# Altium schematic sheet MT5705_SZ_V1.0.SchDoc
size A4; PageSetup: Record=PageOptions¦CenterHorizontal=True¦CenterVertical=True¦PrintScale=1.00¦XCorrection=1.00¦YCorrection=1.00¦PrintKind=0¦BorderSize=5000000¦LeftOffset=0¦BottomOffset=0¦Orientation=2¦PaperLength=1000¦PaperWidth=1000¦Scale=100¦PaperSource=7¦PrintQuality=-4¦MediaType=1¦DitherType=10¦PrintScaleMode=1¦PaperKind=A4¦PaperIndex=9
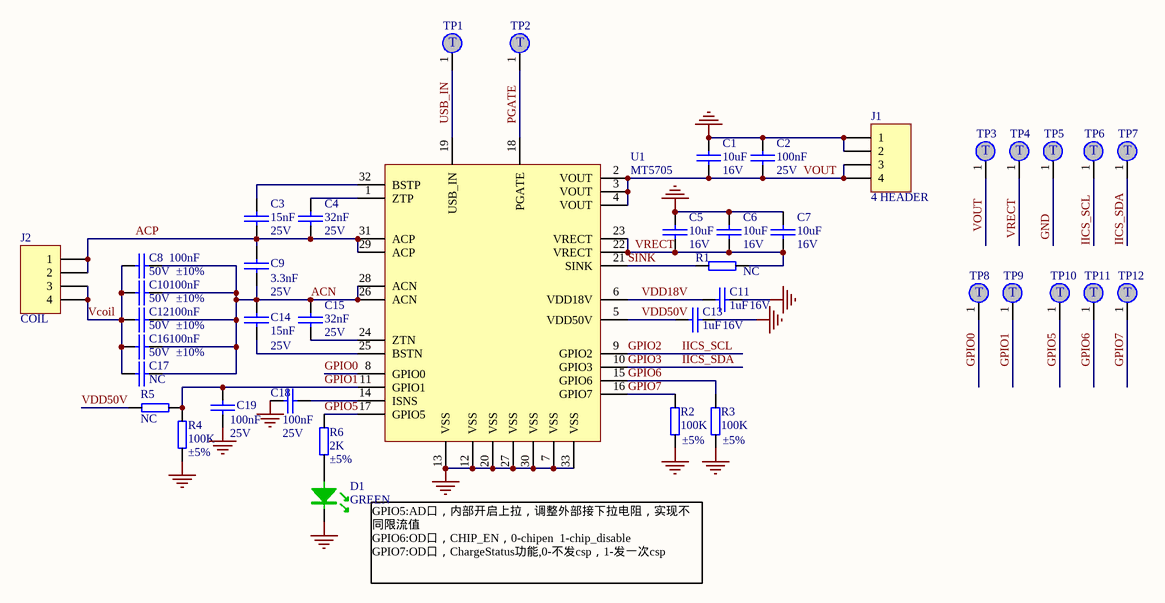
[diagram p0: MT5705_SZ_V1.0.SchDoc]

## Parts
C1  10uF  耐压: 16V  [0603C]
C2  100nF  耐压: 25V  [0402C]
C3  15nF  耐压: 25V  [0402C]
C4  32nF  耐压: 25V  [0402C]
C5  10uF  耐压: 16V  [0603C]
C6  10uF  耐压: 16V  [0603C]
C7  10uF  耐压: 16V  [0603C]
C8  100nF  耐压: 50V  精度: ±10%  [0402C]
C9  3.3nF  耐压: 25V  [0402C]
C10  100nF  耐压: 50V  精度: ±10%  [0402C]
C11  1uF  耐压: 16V  [0402C]
C12  100nF  耐压: 50V  精度: ±10%  [0402C]
C13  1uF  耐压: 16V  [0402C]
C14  15nF  耐压: 25V  [0402C]
C15  32nF  耐压: 25V  [0402C]
C16  100nF  耐压: 50V  精度: ±10%  [0402C]
C17  NC  [0402C]
C18  100nF  耐压: 25V  [0402C]
C19  100nF  耐压: 25V  [0402C]
D1  GREEN  [D0603]
J1  4 HEADER  [SIP4-2.00mm]
J2  COIL  [SIP4-2.00mm]
R1  NC  [0603R]
R2  100K  精度: ±5%  [0402R]
R3  100K  精度: ±5%  [0402R]
R4  100K  精度: ±5%  [0402R]
R5  NC  [0402R]
R6  2K  精度: ±5%  [0402R]
TP1  (no value)  [TEST-PAD-S]
TP2  (no value)  [TEST-PAD-S]
TP3  (no value)  [TEST-PAD-S]
TP4  (no value)  [TEST-PAD-S]
TP5  (no value)  [TEST-PAD-S]
TP6  (no value)  [TEST-PAD-S]
TP7  (no value)  [TEST-PAD-S]
TP8  (no value)  [TEST-PAD-S]
TP9  (no value)  [TEST-PAD-S]
TP10  (no value)  [TEST-PAD-S]
TP11  (no value)  [TEST-PAD-S]
TP12  (no value)  [TEST-PAD-S]
U1  MT5705  [QFN32-EPAD]

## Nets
GND: C1.2 C2.1 C5.2 C6.2 C7.2 C11.2 C13.2 C18.1 C19.1 D1.K J1.1 J1.2 R2.1 R3.1 R4.1 TP5.1 U1.7(VSS) U1.12(VSS) U1.13(VSS) U1.20(VSS) U1.27(VSS) U1.30(VSS) U1.33(VSS)
ACN: C8.1 C9.2 C10.1 C12.1 C14.1 C15.1 C16.1 C17.1 U1.26(ACN) U1.28(ACN)
ACP: C3.2 C4.2 C9.1 J2.1 J2.2 U1.29(ACP) U1.31(ACP)
GPIO0: TP8.1 U1.8(GPIO0)
GPIO1: C19.2 R4.2 R5.1 TP9.1 U1.11(GPIO1)
GPIO2: TP6.1 U1.9(GPIO2)  [also labelled IICS_SCL]
GPIO3: TP7.1 U1.10(GPIO3)  [also labelled IICS_SDA]
GPIO5: R6.2 TP10.1 U1.17(GPIO5)
GPIO6: R3.2 TP11.1 U1.15(GPIO6)
GPIO7: R2.2 TP12.1 U1.16(GPIO7)
PGATE: TP2.1 U1.18(PGATE)
SINK: R1.1 U1.21(SINK)
USB_IN: TP1.1 U1.19(USB_IN)
Vcoil: C8.2 C10.2 C12.2 C16.2 C17.2 J2.3 J2.4
VDD18V: C11.1 U1.6(VDD18V)
VDD50V: C13.1 R5.2 U1.5(VDD50V)
VOUT: C1.1 C2.2 J1.3 J1.4 TP3.1 U1.2(VOUT) U1.3(VOUT) U1.4(VOUT)
VRECT: C5.1 C6.1 C7.1 R1.2 TP4.1 U1.22(VRECT) U1.23(VRECT)
NetC3_1: C3.1 U1.32(BSTP)
NetC4_1: C4.1 U1.1(ZTP)
NetC14_2: C14.2 U1.25(BSTN)
NetC15_2: C15.2 U1.24(ZTN)
NetC18_2: C18.2 U1.14(ISNS)
NetD1_A: D1.A R6.1

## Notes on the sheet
- GPIO5:AD口，内部开启上拉，调整外部接下拉电阻，实现不同限流值
  GPIO6:OD口，CHIP_EN，0-chipen  1-chip_disable
  GPIO7:OD口，ChargeStatus功能,0-不发csp，1-发一次csp

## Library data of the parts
C1-C16 C18 C19 = CAP: Capacitor
C17 = CAP: Capacitor; 耐压: 50V; 精度: ±10%
D1 = LED-GREEN
J1 J2 = 4 HEADER: 4 Pin Header
R1-R4 R6 = RES
R5 = RES: 精度: ±5%
TP1-TP12 = TEST-PAD
U1 = MT5705_QFN32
